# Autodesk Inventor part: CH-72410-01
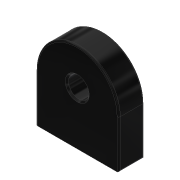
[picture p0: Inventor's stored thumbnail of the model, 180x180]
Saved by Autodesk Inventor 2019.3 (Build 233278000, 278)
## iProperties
Created: 2012-10
Part Number: CH-72410-01
Material: Ogólny
Document SubType Name: Modeling
Designer: CADENGINEERING4
Density: 1 g/cm^3
Appearance: Gładki — czarny
Author: CADENGINEERING4
Revision Number: ÈÎºÎ
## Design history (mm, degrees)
feature "µ¹½Ç1"
node "Bryła1"
